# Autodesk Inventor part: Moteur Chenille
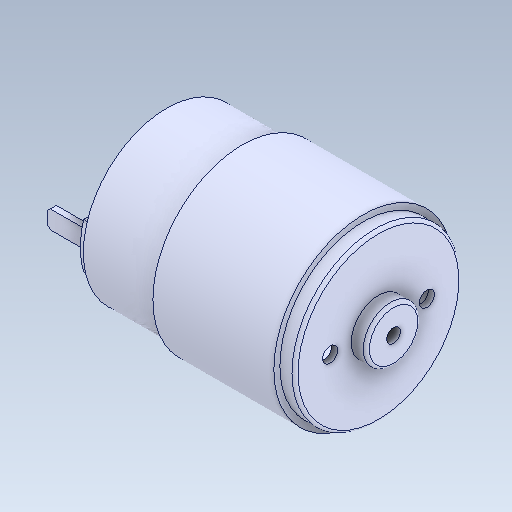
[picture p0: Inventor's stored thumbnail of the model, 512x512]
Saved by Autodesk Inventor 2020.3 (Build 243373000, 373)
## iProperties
Created: 2018-09
Part Number: Moteur Chenille
Material: Générique
Document SubType Name: Modeling
Designer: ficho
Density: 1 g/cm^3
Appearance: Par défaut
Mass: 7.04759 g
Surface Area: 83.9005 cm^2
Volume: 7.04759 cm^3
Sending System: SolidWorks 2015
Last Author: adrien
Last Saved: 2019-01-14
Author: ficho
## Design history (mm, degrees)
feature "Enlèvement de matière-Révolution1[2]"
feature "Enlèv. mat.-Extru.4"
node "Solide1"
node "Solide2"
